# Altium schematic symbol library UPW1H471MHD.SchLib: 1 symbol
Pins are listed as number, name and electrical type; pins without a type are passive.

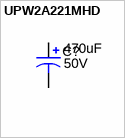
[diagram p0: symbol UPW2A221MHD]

## UPW2A221MHD
designator C?  value 470uF  Value2Displayed: 50V  (hidden comment: UPW2A221MHD)
CAP, AL, 470µF, 50V, +/- 20%, Radial; Manufacturer: Nichicon; Tolerance_%: 20; VDC_V: 50
footprint UPW1H471MHD (12.5Dx20T-5mmLS)
pins: 1 +, 2 -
